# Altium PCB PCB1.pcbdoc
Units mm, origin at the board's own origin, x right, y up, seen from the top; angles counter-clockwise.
Board outline 108.97 x 102.36 mm, 2 copper layers (Top Layer, Bottom Layer); 0 components, 2 nets, 36 pads, 176 vias.
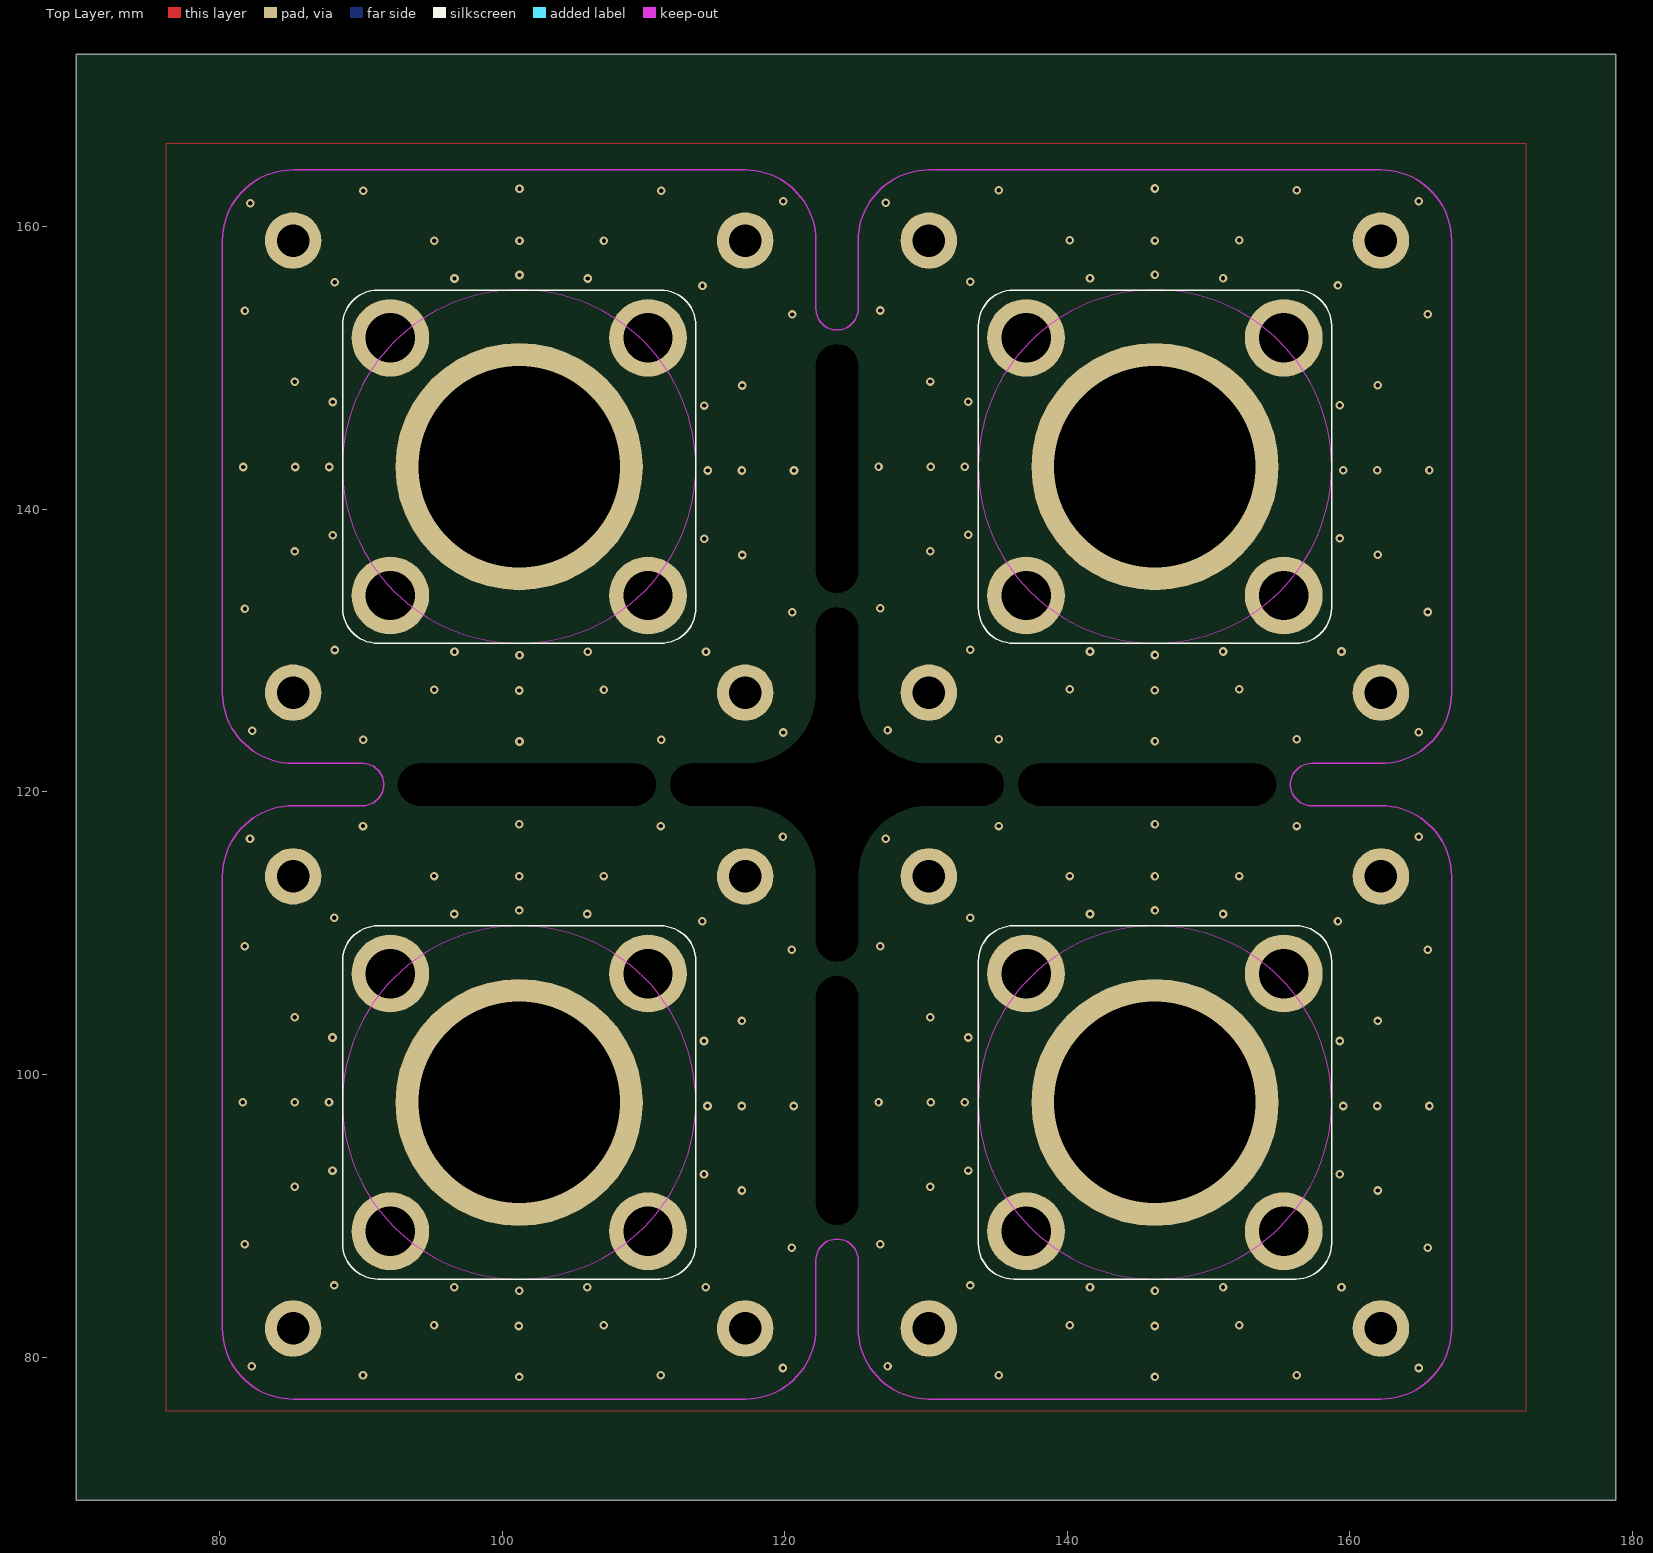
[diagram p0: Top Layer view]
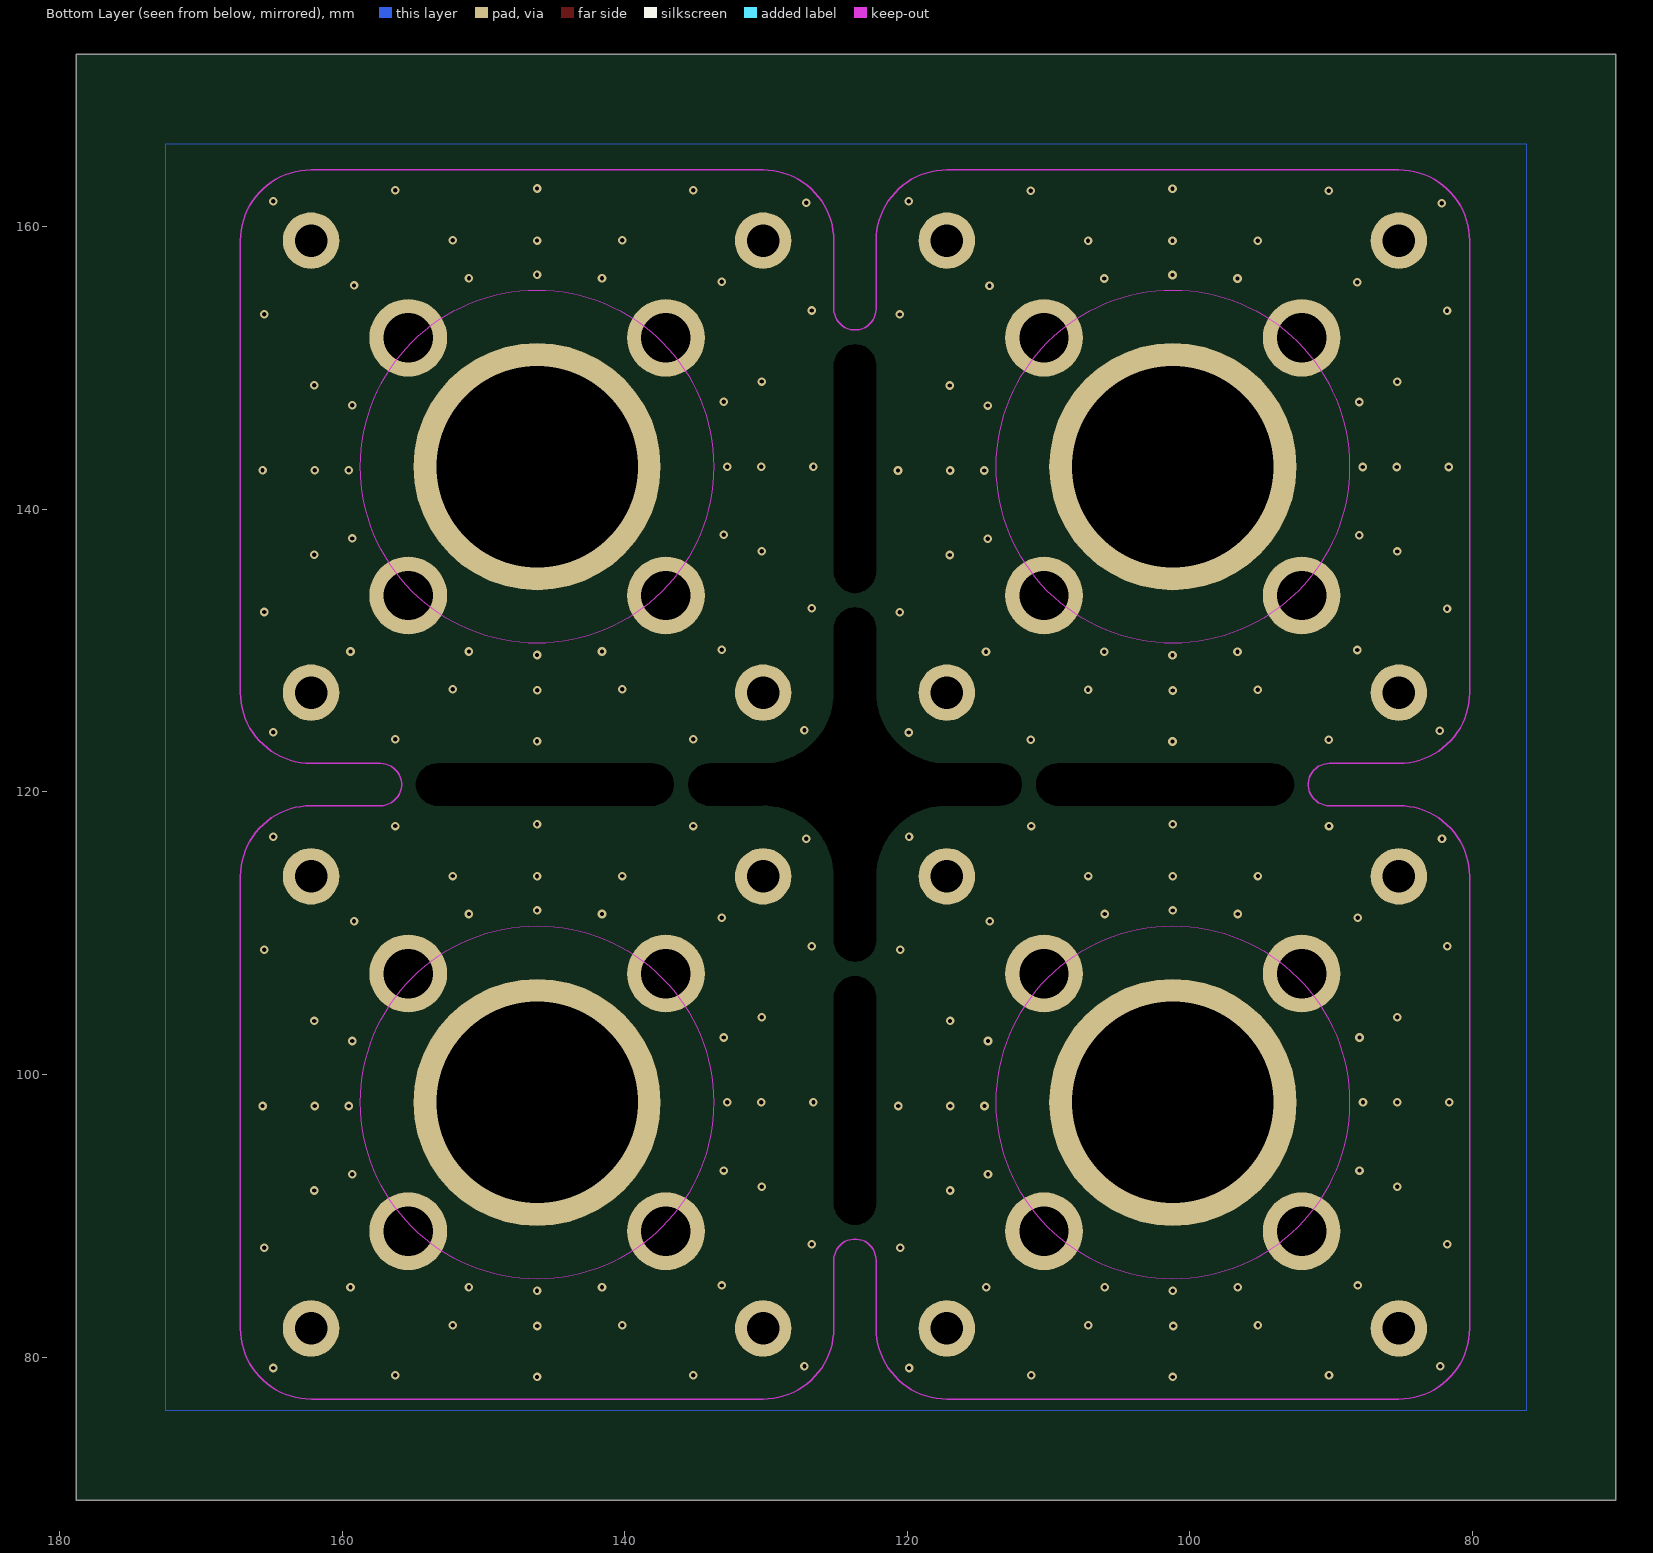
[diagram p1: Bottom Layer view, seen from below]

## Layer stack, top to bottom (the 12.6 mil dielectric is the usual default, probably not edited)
Top Layer: signal copper (thickness not stored)
Dielectric: dielectric 0.32, FR-4, Dk 4.8
Bottom Layer: signal copper (thickness not stored)

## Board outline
178.816,69.85 69.85,69.85 69.85,172.212 178.816,172.212
cut-out: 118.348,159.023 ccw(c117.198,159.023) 116.048,159.023 ccw(c117.198,159.023)
cut-out: 86.348,159.023 ccw(c85.198,159.023) 84.048,159.023 ccw(c85.198,159.023)
cut-out: 118.348,127.023 ccw(c117.198,127.023) 116.048,127.023 ccw(c117.198,127.023)
cut-out: 86.348,127.023 ccw(c85.198,127.023) 84.048,127.023 ccw(c85.198,127.023)
cut-out: 108.323,143.023 ccw(c101.198,143.023) 94.073,143.023 ccw(c101.198,143.023)
cut-out: 112.068,152.143 ccw(c110.318,152.143) 108.568,152.143 ccw(c110.318,152.143)
cut-out: 93.828,152.143 ccw(c92.078,152.143) 90.328,152.143 ccw(c92.078,152.143)
cut-out: 112.068,133.903 ccw(c110.318,133.903) 108.568,133.903 ccw(c110.318,133.903)
cut-out: 93.828,133.903 ccw(c92.078,133.903) 90.328,133.903 ccw(c92.078,133.903)
cut-out: 163.298,159.023 ccw(c162.198,159.023) 161.098,159.023 ccw(c162.198,159.023)
cut-out: 131.348,159.023 ccw(c130.198,159.023) 129.048,159.023 ccw(c130.198,159.023)
cut-out: 163.348,127.023 ccw(c162.198,127.023) 161.048,127.023 ccw(c162.198,127.023)
cut-out: 131.348,127.023 ccw(c130.198,127.023) 129.048,127.023 ccw(c130.198,127.023)
cut-out: 153.323,143.023 ccw(c146.198,143.023) 139.073,143.023 ccw(c146.198,143.023)
cut-out: 157.068,152.143 ccw(c155.318,152.143) 153.568,152.143 ccw(c155.318,152.143)
cut-out: 138.828,152.143 ccw(c137.078,152.143) 135.328,152.143 ccw(c137.078,152.143)
cut-out: 157.068,133.903 ccw(c155.318,133.903) 153.568,133.903 ccw(c155.318,133.903)
cut-out: 138.828,133.903 ccw(c137.078,133.903) 135.328,133.903 ccw(c137.078,133.903)
cut-out: 118.298,114.023 ccw(c117.198,114.023) 116.098,114.023 ccw(c117.198,114.023)
cut-out: 86.348,114.023 ccw(c85.198,114.023) 84.048,114.023 ccw(c85.198,114.023)
cut-out: 118.348,82.023 ccw(c117.198,82.023) 116.048,82.023 ccw(c117.198,82.023)
cut-out: 86.348,82.023 ccw(c85.198,82.023) 84.048,82.023 ccw(c85.198,82.023)
cut-out: 108.323,98.023 ccw(c101.198,98.023) 94.073,98.023 ccw(c101.198,98.023)
cut-out: 112.068,107.143 ccw(c110.318,107.143) 108.568,107.143 ccw(c110.318,107.143)
cut-out: 93.828,107.143 ccw(c92.078,107.143) 90.328,107.143 ccw(c92.078,107.143)
cut-out: 112.068,88.903 ccw(c110.318,88.903) 108.568,88.903 ccw(c110.318,88.903)
cut-out: 93.828,88.903 ccw(c92.078,88.903) 90.328,88.903 ccw(c92.078,88.903)
cut-out: 163.348,114.023 ccw(c162.198,114.023) 161.048,114.023 ccw(c162.198,114.023)
cut-out: 131.348,114.023 ccw(c130.198,114.023) 129.048,114.023 ccw(c130.198,114.023)
cut-out: 163.348,82.023 ccw(c162.198,82.023) 161.048,82.023 ccw(c162.198,82.023)
cut-out: 131.348,82.023 ccw(c130.198,82.023) 129.048,82.023 ccw(c130.198,82.023)
cut-out: 153.323,98.023 ccw(c146.198,98.023) 139.073,98.023 ccw(c146.198,98.023)
cut-out: 157.068,107.143 ccw(c155.318,107.143) 153.568,107.143 ccw(c155.318,107.143)
cut-out: 138.828,107.143 ccw(c137.078,107.143) 135.328,107.143 ccw(c137.078,107.143)
cut-out: 157.068,88.903 ccw(c155.318,88.903) 153.568,88.903 ccw(c155.318,88.903)
cut-out: 138.828,88.903 ccw(c137.078,88.903) 135.328,88.903 ccw(c137.078,88.903)
cut-out: 163.348,159.023 ccw(c162.198,159.023) 161.048,159.023 ccw(c162.198,159.023)
cut-out: 163.298,114.023 ccw(c162.198,114.023) 161.098,114.023 ccw(c162.198,114.023)
cut-out: 118.348,114.023 ccw(c117.198,114.023) 116.048,114.023 ccw(c117.198,114.023)
cut-out: 153.284,122.023 138.012,122.023 ccw(c138.012,120.523) 138.012,119.023 153.284,119.023 ccw(c153.284,120.523)
cut-out: 125.198,90.847 125.198,105.472 ccw(c123.698,105.472) 122.198,105.472 122.198,90.847 ccw(c123.698,90.847)
cut-out: 94.112,119.023 109.384,119.023 ccw(c109.384,120.523) 109.384,122.023 94.112,122.023 ccw(c94.112,120.523)
cut-out: 122.198,150.199 122.198,135.574 ccw(c123.698,135.574) 125.198,135.574 125.198,150.199 ccw(c123.698,150.199)
cut-out: 122.198,114.023 122.198,109.472 ccw(c123.698,109.472) 125.198,109.472 125.198,114.023 cw(c130.198,114.023) 130.198,119.023 134.012,119.023 ccw(c134.012,120.523) 134.012,122.023 130.198,122.023 cw(c130.198,127.023) 125.198,127.023 125.198,131.574 ccw(c123.698,131.574) 122.198,131.574 122.198,127.023 cw(c117.198,127.023) 117.198,122.023 113.384,122.023 ccw(c113.384,120.523) 113.384,119.023 117.198,119.023 cw(c117.198,114.023)

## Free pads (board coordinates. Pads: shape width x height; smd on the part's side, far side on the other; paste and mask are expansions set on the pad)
  round 4 hole 2.3: 1(85.198,82.023) 1(85.198,114.023) 1(85.198,127.023) 1(85.198,159.023) 1(117.198,82.023) 1(117.198,114.023) 1(117.198,127.023) 1(117.198,159.023) 1(130.198,82.023) 1(130.198,114.023) 1(130.198,127.023) 1(130.198,159.023) 1(162.198,82.023) 1(162.198,114.023) 1(162.198,127.023) 1(162.198,159.023)
  round 5.5 hole 3.5: 1(92.078,88.903) 1(92.078,107.143) 1(92.078,133.903) 1(92.078,152.143) 1(110.318,88.903) 1(110.318,107.143) 1(110.318,133.903) 1(110.318,152.143) 1(137.078,88.903) 1(137.078,107.143) 1(137.078,133.903) 1(137.078,152.143) 1(155.318,88.903) 1(155.318,107.143) 1(155.318,133.903) 1(155.318,152.143)
  round 17.5 hole 14.25: 1(101.198,98.023) 1(101.198,143.023) 1(146.198,98.023) 1(146.198,143.023)

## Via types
v1: diameter 0.61, hole 0.305, Top Layer to Bottom Layer, 176 vias

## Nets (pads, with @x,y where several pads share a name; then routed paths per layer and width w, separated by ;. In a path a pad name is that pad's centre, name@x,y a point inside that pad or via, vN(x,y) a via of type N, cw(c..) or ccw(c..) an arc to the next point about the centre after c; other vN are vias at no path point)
GND: pad.1@85.198,82.023 pad.1@85.198,114.023 pad.1@85.198,127.023 pad.1@85.198,159.023 pad.1@92.078,88.903 pad.1@92.078,107.143 pad.1@92.078,133.903 pad.1@92.078,152.143 pad.1@110.318,88.903 pad.1@110.318,107.143 pad.1@110.318,133.903 pad.1@110.318,152.143 pad.1@117.198,82.023 pad.1@117.198,114.023 pad.1@117.198,127.023 pad.1@117.198,159.023 pad.1@130.198,82.023 pad.1@130.198,114.023 pad.1@130.198,127.023 pad.1@130.198,159.023 pad.1@137.078,88.903 pad.1@137.078,107.143 pad.1@137.078,133.903 pad.1@137.078,152.143 pad.1@155.318,88.903 pad.1@155.318,107.143 pad.1@155.318,133.903 pad.1@155.318,152.143 pad.1@162.198,82.023 pad.1@162.198,114.023 pad.1@162.198,127.023 pad.1@162.198,159.023
  other v1: 101.198,78.592 146.198,78.592 90.149,78.719 111.231,78.719 135.149,78.719 156.231,78.719 119.867,79.227 164.867,79.227 82.275,79.354 127.275,79.354 101.177,82.2 146.177,82.2 95.177,82.256 107.177,82.256 140.177,82.256 152.177,82.256 101.198,84.688 146.198,84.688 96.601,84.942 106.024,84.942 114.406,84.942 141.601,84.942 151.024,84.942 159.406,84.942 88.117,85.069 133.117,85.069 120.502,87.736 165.502,87.736 81.767,87.99 126.767,87.99 116.965,91.79 161.965,91.79 85.304,92.044 130.304,92.044 114.279,92.943 159.279,92.943 87.99,93.197 132.99,93.197 114.533,97.769 116.946,97.769 120.629,97.769 159.533,97.769 161.946,97.769 165.629,97.769 81.64,98.023 85.323,98.023 87.736,98.023 126.64,98.023 130.323,98.023 132.736,98.023 114.279,102.366 159.279,102.366 87.99,102.62 132.99,102.62 116.965,103.79 161.965,103.79 85.304,104.044 130.304,104.044 120.502,108.818 165.502,108.818 81.767,109.072 126.767,109.072 114.152,110.85 159.152,110.85 88.117,111.104 133.117,111.104 96.601,111.358 106.024,111.358 141.601,111.358 151.024,111.358 101.198,111.612 146.198,111.612 101.198,114.025 146.198,114.025 95.177,114.044 107.177,114.044 140.177,114.044 152.177,114.044 82.148,116.692 127.148,116.692 119.867,116.819 164.867,116.819 90.149,117.581 111.231,117.581 135.149,117.581 156.231,117.581 101.198,117.708 146.198,117.708 101.219,123.571 146.198,123.592 90.17,123.698 111.252,123.698 135.149,123.719 156.231,123.719 119.888,124.206 164.867,124.227 82.296,124.333 127.275,124.354 101.198,127.179 146.177,127.2 95.198,127.235 107.198,127.235 140.177,127.256 152.177,127.256 101.219,129.667 146.198,129.688 96.622,129.921 106.045,129.921 114.427,129.921 141.601,129.942 151.024,129.942 159.406,129.942 88.138,130.048 133.117,130.069 120.523,132.715 165.502,132.736 81.788,132.969 126.767,132.99 116.986,136.769 161.965,136.79 85.325,137.023 130.304,137.044 114.3,137.922 159.279,137.943 88.011,138.176 132.99,138.197 114.554,142.748 116.967,142.748 120.65,142.748 159.533,142.769 161.946,142.769 165.629,142.769 81.661,143.002 85.344,143.002 87.757,143.002 126.64,143.023 130.323,143.023 132.736,143.023 114.3,147.345 159.279,147.366 88.011,147.599 132.99,147.62 116.986,148.769 161.965,148.79 85.325,149.023 130.304,149.044 120.523,153.797 165.502,153.818 81.788,154.051 126.767,154.072 114.173,155.829 159.152,155.85 88.138,156.083 133.117,156.104 96.622,156.337 106.045,156.337 141.601,156.358 151.024,156.358 101.219,156.591 146.198,156.612 101.219,159.004 95.198,159.023 107.198,159.023 146.198,159.025 140.177,159.044 152.177,159.044 82.169,161.671 127.148,161.692 119.888,161.798 164.867,161.819 90.17,162.56 111.252,162.56 135.149,162.581 156.231,162.581 101.219,162.687 146.198,162.708
"": pad.1@101.198,98.023 pad.1@101.198,143.023 pad.1@146.198,98.023 pad.1@146.198,143.023

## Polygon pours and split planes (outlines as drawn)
GND on Top Layer (solid, remove dead copper, pour order 0): 76.2,76.2 172.466,76.2 172.466,165.862 76.2,165.862
GND on Bottom Layer (solid, remove dead copper, pour order 1): 76.2,76.2 172.466,76.2 172.466,165.862 76.2,165.862

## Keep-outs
Board Outline Layer:
  lines w0.1 net "": 80.198,82.023 ccw(c85.198,82.023) 85.198,77.023 117.198,77.023 ccw(c117.198,82.023) 122.198,82.023 122.198,86.847 cw(c123.698,86.847) 125.198,86.847 125.198,82.023 ccw(c130.198,82.023) 130.198,77.023 162.198,77.023 ccw(c162.198,82.023) 167.198,82.023 167.198,114.023 ccw(c162.198,114.023) 162.198,119.023 157.284,119.023 cw(c157.284,120.523) 157.284,122.023 162.198,122.023 ccw(c162.198,127.023) 167.198,127.023 167.198,159.023 ccw(c162.198,159.023) 162.198,164.023 130.198,164.023 ccw(c130.198,159.023) 125.198,159.023 125.198,154.199 cw(c123.698,154.199) 122.198,154.199 122.198,159.023 ccw(c117.198,159.023) 117.198,164.023 85.198,164.023 ccw(c85.198,159.023) 80.198,159.023 80.198,127.023 ccw(c85.198,127.023) 85.198,122.023 90.112,122.023 cw(c90.112,120.523) 90.112,119.023 85.198,119.023 ccw(c85.198,114.023) 80.198,114.023 80.198,82.023
Multi-Layer:
  region net "": 113.698,143.023 ccw(c101.198,143.023) 88.698,143.023 ccw(c101.198,143.023)
  region net "": 158.698,143.023 ccw(c146.198,143.023) 133.698,143.023 ccw(c146.198,143.023)
  region net "": 158.698,98.023 ccw(c146.198,98.023) 133.698,98.023 ccw(c146.198,98.023)
  region net "": 113.698,98.023 ccw(c101.198,98.023) 88.698,98.023 ccw(c101.198,98.023)

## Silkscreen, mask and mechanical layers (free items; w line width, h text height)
Top Silkscreen Layer:
  lines w0.1 net "": 88.698,88.023 88.698,108.023 cw(c91.198,108.023) 91.198,110.523 111.198,110.523 cw(c111.198,108.023) 113.698,108.023 113.698,88.023 cw(c111.198,88.023) 111.198,85.523 91.198,85.523 cw(c91.198,88.023) 88.698,88.023 ; 88.698,133.023 88.698,153.023 cw(c91.198,153.023) 91.198,155.523 111.198,155.523 cw(c111.198,153.023) 113.698,153.023 113.698,133.023 cw(c111.198,133.023) 111.198,130.523 91.198,130.523 cw(c91.198,133.023) 88.698,133.023 ; 133.698,88.023 133.698,108.023 cw(c136.198,108.023) 136.198,110.523 156.198,110.523 cw(c156.198,108.023) 158.698,108.023 158.698,88.023 cw(c156.198,88.023) 156.198,85.523 136.198,85.523 cw(c136.198,88.023) 133.698,88.023 ; 133.698,133.023 133.698,153.023 cw(c136.198,153.023) 136.198,155.523 156.198,155.523 cw(c156.198,153.023) 158.698,153.023 158.698,133.023 cw(c156.198,133.023) 156.198,130.523 136.198,130.523 cw(c136.198,133.023) 133.698,133.023
Mechanical Layer:
  circle w0.025 net "": c117.198,159.023 r1.15
  circle w0.025 net "": c85.198,159.023 r1.15
  circle w0.025 net "": c117.198,127.023 r1.15
  circle w0.025 net "": c85.198,127.023 r1.15
  circle w0.025 net "": c101.198,143.023 r7.125
  circle w0.025 net "": c110.318,152.143 r1.75
  circle w0.025 net "": c92.078,152.143 r1.75
  circle w0.025 net "": c110.318,133.903 r1.75
  circle w0.025 net "": c92.078,133.903 r1.75
  circle w0.025 net "": c162.198,159.023 r1.1
  circle w0.025 net "": c130.198,159.023 r1.15
  circle w0.025 net "": c162.198,127.023 r1.15
  circle w0.025 net "": c130.198,127.023 r1.15
  circle w0.025 net "": c146.198,143.023 r7.125
  circle w0.025 net "": c155.318,152.143 r1.75
  circle w0.025 net "": c137.078,152.143 r1.75
  circle w0.025 net "": c155.318,133.903 r1.75
  circle w0.025 net "": c137.078,133.903 r1.75
  circle w0.025 net "": c117.198,114.023 r1.1
  circle w0.025 net "": c85.198,114.023 r1.15
  circle w0.025 net "": c117.198,82.023 r1.15
  circle w0.025 net "": c85.198,82.023 r1.15
  circle w0.025 net "": c101.198,98.023 r7.125
  circle w0.025 net "": c110.318,107.143 r1.75
  circle w0.025 net "": c92.078,107.143 r1.75
  circle w0.025 net "": c110.318,88.903 r1.75
  circle w0.025 net "": c92.078,88.903 r1.75
  circle w0.025 net "": c162.198,114.023 r1.15
  circle w0.025 net "": c130.198,114.023 r1.15
  circle w0.025 net "": c162.198,82.023 r1.15
  circle w0.025 net "": c130.198,82.023 r1.15
  circle w0.025 net "": c146.198,98.023 r7.125
  circle w0.025 net "": c155.318,107.143 r1.75
  circle w0.025 net "": c137.078,107.143 r1.75
  circle w0.025 net "": c155.318,88.903 r1.75
  circle w0.025 net "": c137.078,88.903 r1.75
  circle w0.025 net "": c162.198,159.023 r1.15
  circle w0.025 net "": c162.198,114.023 r1.1
  circle w0.025 net "": c117.198,114.023 r1.15
  lines w0.025 net "": 94.112,119.023 109.384,119.023 ccw(c109.384,120.523) 109.384,122.023 94.112,122.023 ccw(c94.112,120.523) 94.112,119.023 ; 113.384,119.023 cw(c113.384,120.523) 113.384,122.023 117.198,122.023 ccw(c117.198,127.023) 122.198,127.023 122.198,131.574 cw(c123.698,131.574) 125.198,131.574 125.198,127.023 ccw(c130.198,127.023) 130.198,122.023 134.012,122.023 cw(c134.012,120.523) 134.012,119.023 130.198,119.023 ccw(c130.198,114.023) 125.198,114.023 125.198,109.472 cw(c123.698,109.472) 122.198,109.472 122.198,114.023 ccw(c117.198,114.023) 117.198,119.023 113.384,119.023 ; 122.198,90.847 122.198,105.472 cw(c123.698,105.472) 125.198,105.472 125.198,90.847 cw(c123.698,90.847) 122.198,90.847 ; 122.198,135.574 122.198,150.199 cw(c123.698,150.199) 125.198,150.199 125.198,135.574 cw(c123.698,135.574) 122.198,135.574 ; 138.012,119.023 cw(c138.012,120.523) 138.012,122.023 153.284,122.023 cw(c153.284,120.523) 153.284,119.023 138.012,119.023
